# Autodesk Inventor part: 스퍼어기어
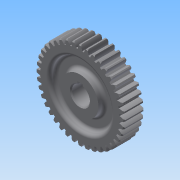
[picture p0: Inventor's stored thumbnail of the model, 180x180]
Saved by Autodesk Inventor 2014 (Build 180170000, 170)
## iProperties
Created: 2020-11
Part Number: 스퍼어기어
Material: 일반
Document SubType Name: Modeling
Designer: NET
Density: 1 g/cm^3
Appearance: 기본값
Author: NET
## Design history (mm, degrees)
sketch "스케치1"
  geometry: L1 (-9.5, 0)-(9.5, 0); L2 (-9.5, 8.5)-(-9.5, 17.5); L3 (-9.5, 17.5)-(-3.5, 17.5); L4 (-3.5, 17.5)-(-3.5, 29); L5 (-3.5, 29)-(-9.5, 29); L6 (-9.5, 29)-(-9.5, 37.5); L7 (-9.5, 37.5)-(9.5, 37.5); L8 (9.5, 37.5)-(9.5, 29); L9 (9.5, 29)-(3.5, 29); L10 (3.5, 29)-(3.5, 17.5); L11 (3.5, 17.5)-(9.5, 17.5); L12 (9.5, 17.5)-(9.5, 8.5); L13 (9.5, 8.5)-(-9.5, 8.5); 2 further points
  constraints: 26 end point, 8 parallel, 4 vertical alignment, 2 collinear, 2 horizontal alignment, 2 perpendicular, 1 coincident, 1 horizontal, 1 midpoint
  dimensions: "d0" = 19 distance of L1.start L1.end; "d1" = 17 diameter of L13 L1; "d2" = 35 diameter of L11 L1; "d3" = 58 diameter of L9 L1; "d4" = 75 diameter of L7 L1; "d5" = 7 distance between parallel lines of L10 L4; "d6" = 6 distance from line of L2.end L4
revolve "회전1" sketch "스케치1" stored, may be unused: angle "d7" = 90 deg
sketch "스케치2"
  geometry: C1 r 29 at (0, 0) reference; A1 r 37.5 centre (0, 0) between (-2.07, 37.443) and (2.07, 37.443) reference; A2 r 40 centre (0, 0) between (1.57, 39.969) and (-1.57, 39.969); A3 r 42 centre (0, 0) between (0.57, 41.996) and (-0.57, 41.996); A4 r 9.223 centre (7.138, 36.933) between (-0.57, 41.996) and (-2.07, 37.443); A5 r 9.223 centre (-7.138, 36.933) between (2.07, 37.443) and (0.57, 41.996); 2 further points
  constraints: 14 point on circle, 4 centre point, 2 coincident, 2 vertical alignment, 1 equal radius
  dimensions: "d8" = 40 radius of A2; "d9" = 42 radius of A3; "d10" = 0.5 horizontal distance of A1.start A2.end; "d11" = 1 horizontal distance of A2.end A3.end; "d12" = 1.57 horizontal distance of point (0, 42) A2.end
extrude "돌출1" join sketch "스케치2" distance "d13" = 19; taper "d14" = 0 deg
chamfer "모따기1" distance "d15" = 1; stored, may be unused: second distance "d16" = 2, angle "d17" = 45 deg
sketch "스케치3"
  geometry: L1 (-2.5, 10.8)-(2.5, 10.8); L2 (2.5, 10.8)-(2.5, 8.124); L3 (2.5, 8.124)-(-2.5, 8.124); L4 (-2.5, 8.124)-(-2.5, 10.8); C1 r 17.5 at (0, 0) reference; 2 further points
  constraints: 8 end point, 2 parallel, 1 horizontal, 1 midpoint, 1 perpendicular, 1 vertical alignment, 2 other
  dimensions: "d22" = 19.3 dimension on L1; "d23" = 5 distance of L1.start L1.end
extrude "돌출2" cut sketch "스케치3" stored distance "d24" = 19; taper "d25" = 0 deg
fillet "모깎기1" dims "d26" = 3
chamfer "모따기2" distance "d27" = 1; stored, may be unused: second distance "d28" = 2, angle "d29" = 45 deg
node "솔리드1"
pattern_circular "원형 패턴1" dims angle "d19" = 360 deg
